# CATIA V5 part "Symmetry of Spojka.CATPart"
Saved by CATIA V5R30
Part number: Symmetry of Spojka
Bounding box of the stored display mesh (mm): x -8.66 to 8.66, y -7.5 to 7.5, z -9 to 17
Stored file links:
  E:\Bakalarka\Model\Forma_v7\Symmetry of Spojka.CATPart
  E:\Bakalarka\Model\Forma_v7\Spojka_1.CATPart
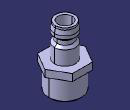
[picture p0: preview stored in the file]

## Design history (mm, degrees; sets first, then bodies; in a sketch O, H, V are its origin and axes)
Body1 (main body)
  Body2 "Body from original PartBody"
    Solid1: linked copy from another document
  Assemble1: tool Body2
